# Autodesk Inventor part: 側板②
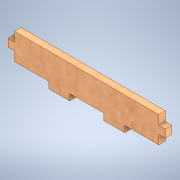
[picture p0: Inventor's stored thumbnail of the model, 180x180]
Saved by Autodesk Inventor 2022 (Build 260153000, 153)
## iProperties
Created: 2024-11
Part Number: 側板②
Material: MDF 中密度繊維ボード
Document SubType Name: Modeling
Designer: shimizu
Density: 0.8 g/cm^3
Appearance: サクラ材 - ナチュラル 抑えた光沢
Author: shimizu
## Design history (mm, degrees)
sketch "スケッチ1"
  geometry: L1 (-25.358, 1.343)-(29.642, 1.343); L2 (-4.358, -8.657)-(-4.358, -11.157); L3 (-4.358, -11.157)-(-12.358, -11.157); L4 (-12.358, -11.157)-(-12.358, -8.657); L5 (16.642, -8.657)-(16.642, -11.157); L6 (16.642, -11.157)-(8.642, -11.157); L7 (8.642, -11.157)-(8.642, -8.657); L8 (-25.358, -2.157)-(-27.858, -2.157); L9 (-27.858, -2.157)-(-27.858, -5.157); L10 (-27.858, -5.157)-(-25.358, -5.157); L11 (29.642, -2.157)-(32.142, -2.157); L12 (32.142, -2.157)-(32.142, -5.157); L13 (32.142, -5.157)-(29.642, -5.157); L14 (-25.358, -8.657)-(-25.358, -5.157); L15 (-25.358, -2.157)-(-25.358, 1.343); L16 (29.642, 1.343)-(29.642, -2.157); L17 (29.642, -5.157)-(29.642, -8.657); L18 (29.642, -8.657)-(16.642, -8.657); L19 (8.642, -8.657)-(-4.358, -8.657); L20 (-12.358, -8.657)-(-25.358, -8.657); 1 further point
  constraints: 40 end point, 11 parallel, 4 perpendicular, 3 horizontal
  dimensions: "d16" = 13 distance of L17.end L5.start; "d17" = 13 distance of L4.end L14.start; "d18" = 8 distance of L5.end L6.end; "d19" = 8 distance of L2.end L3.end; "d20" = 13 distance of L7.end L2.start; "d21" = 55 distance between parallel lines of L16 L15; "d22" = 60 distance between parallel lines of L12 L9; "d23" = 3.5 distance between parallel lines of L8 L1; "d24" = 3.5 distance between parallel lines of L20 L10; "d25" = 3.5 distance between parallel lines of L11 L1; "d26" = 3.5 distance between parallel lines of L18 L13; "d27" = 3 distance of L8.end L9.end; "d28" = 3 distance of L11.end L12.end
extrude "押し出し1" new body sketch "スケッチ1" distance "d14" = 2.5; taper "d15" = 0 deg
node "ソリッド1"
